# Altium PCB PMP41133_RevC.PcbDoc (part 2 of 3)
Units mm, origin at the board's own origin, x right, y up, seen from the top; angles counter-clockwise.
Board outline 150 x 82 mm, 4 copper layers (Top Layer, Int1 (GND), Int2 (PWR), Bottom Layer), stack 1.369 mm thick; 186 components, 74 nets, 388 pads, 329 vias.
Unrouted connection lines stored in the file: 2.
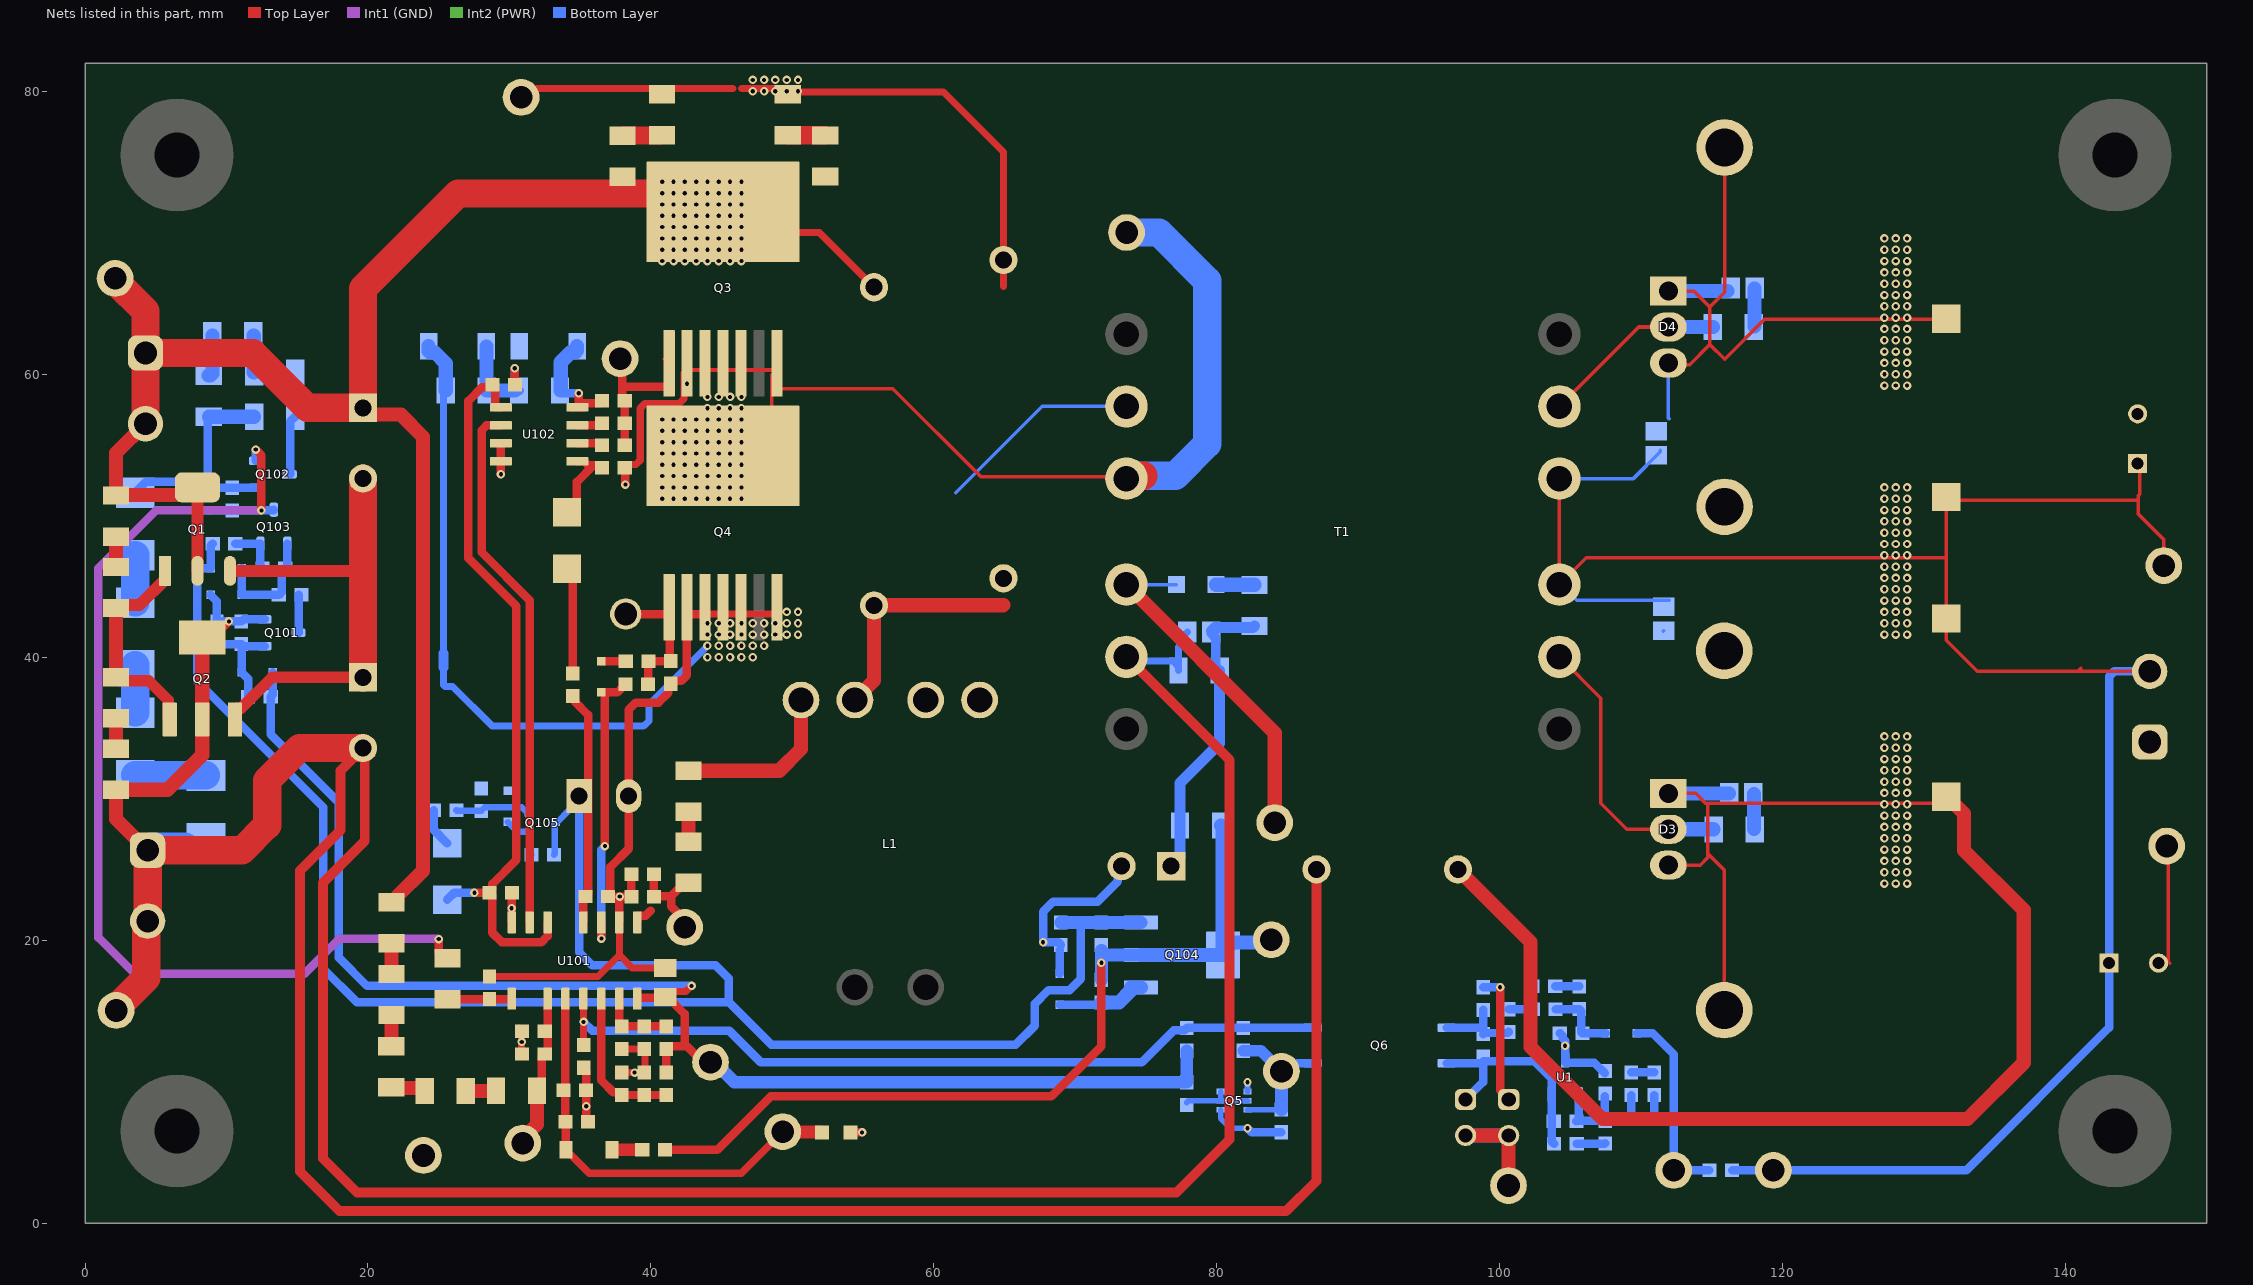
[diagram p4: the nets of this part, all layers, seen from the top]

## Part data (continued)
Q1: library part CMP-0089779-1, "Bipolar (BJT) Transistor NPN 600V 500mA  650mW Surface Mount SOT-223", Collector Base Voltage=600V, Digikey Part Number=1727-2369-1-ND, Emitter Base Voltage=6V, Manufacturer=Nexperia, Operating Temperature Range="to +150°C", Power_W=0.65W
Q2: library part CMP-0000371-2, "Transistor, PNP, 500 V, 0.25 A, AEC-Q101, SOT-223", Manufacturer="NXP Semiconductor", Supplier Part Number 1=568-5575-1-ND, Value1="0.25 A", Value2=300
Q3 Q4: library part CMP-0124581-1, "N-Channel 1200 V 8.1A (Tc) 80W (Tc) Surface Mount PG-TO263-7-12", Digikey Part Number=448-IMBG120R234M2HXTMA1CT-ND, Input Capacitance At Vds="1990pF @ 800V", Manufacturer=Infineon, Mouser Part Number=726-IMBG120R234M2HXT, Operating Temperature Range="-55°C to +175°C", Power_W=335W, Pulse Drain Current=159A, Typ Forward Diode Voltage=4.2V
Q5: library part CMP-0000396-2, "Transistor, Dual NPN, 40 V, 0.2 A, SOT-363", Manufacturer="Diodes Inc.", Supplier Part Number 1=MMDT3904-FDICT-ND, Value1="0.2 A", Value2=300
Q6: library part CMP-0121852-1, "3.75-kVRMS, Single-Channel Opto-Emulator with Analog Transistor Output", Emiiter Collector Voltage=7V, Forward Current=5mA, Manufacturer="Texas Instruments", Operating Temperature Range="to +150°C", Power_TotalModule=290mW, Voltage_Isolation_Vrms=3750Vrms
Q101: library part CMP-0085603-1, "MOSFET, N-CH, 60 V, 0.115 A, AEC-Q101, SOT-23", Alternate Manufacturer=None, Manufacturer="Diodes Inc.", Value1="? ohm", Value2="0.223 nC"
Q102 Q103: library part CMP-0067574-1, "MOSFET, N-CH, 600 V, 0.021 A, AEC-Q101, SOT-23", Alternate Manufacturer=None, Manufacturer="Infineon Technologies", Supplier Part Number 1=BSS126H6327XTSA2CT-ND, Value1="? ohm", Value2="1.4 nC"
Q104: library part CMP-0000393-1, "Transistor, NPN, 60 V, 3 A, SOT-223", Manufacturer=Zetex, Supplier Part Number 1=FZT651CT-ND, Value1="3 A", Value2=300
Q105: library part CMP-0000776-1, "MOSFET, N-CH, 60 V, 0.115 A, SOT-323", Alternate Manufacturer=None, Manufacturer="Diodes Inc.", Supplier Part Number 1=2N7002W-FDICT-ND, Value1=7
R1 R2 R3 R4: library part CMP-0018027-2, "RES, 1.00 M, 1%, 0.25 W, 1206", Manufacturer="Yageo America", Power_W=250mW, Supplier Part Number 1=311-1.00MFRCT-ND, TempCo="100 ppm/C", Tolerance_%=1%, Value2=0.25W, Value_Code=1M00, ValueDisplayed=1.00M
R5 R6: library part CMP-0022170-4, "RES, 1.00, 1%, 0.1 W, AEC-Q200 Grade 0, 0603", Manufacturer=Vishay-Dale, PartNumber=CRCW06031R00FKEA, Power_W=100mW, Supplier Part Number 1=52K8059, TempCo="100 ppm/C", Tolerance_%=1%, Value2=0.1W, Value_Code=1R00, ValueDisplayed=1.00
R7 R8: library part CMP-0022900-4, "RES, 1.00, 1%, 0.1 W, 0603", Manufacturer=Yageo, Power_W=100mW, Supplier Part Number 1=311-1.00HRCT-ND, TempCo="200 ppm/C", Tolerance_%=1%, Value2=0.1W, Value_Code=1R00, ValueDisplayed=1.00
R9 R10: library part CMP-0023167-5, "RES, 51.0 k, 1%, 0.1 W, 0603", Manufacturer=Yageo, Power_W=100mW, Supplier Part Number 1=311-51.0KHRCT-ND, TempCo="100 ppm/C", Tolerance_%=1%, Value2=0.1W, Value_Code=51k0, ValueDisplayed=51.0k
R11: library part CMP-0022938-5, "RES, 240, 1%, 0.1 W, 0603", Manufacturer=Yageo, Power_W=100mW, Supplier Part Number 1=311-240HRCT-ND, TempCo="100 ppm/C", Tolerance_%=1%, Value2=0.1W, Value_Code=240R, ValueDisplayed=240
R12: library part CMP-0018573-3, "RES, 0, 5%, 0.25 W, AEC-Q200 Grade 0, 1206", Manufacturer=Vishay-Dale, Power_W=250mW, Supplier Part Number 1=541-0.0ECT-ND, TempCo="200 ppm/C", Tolerance_%=5%, Value2=0.25W, Value_Code=0000, ValueDisplayed=0
R13 R15: library part CMP-0022872-5, "RES, 1.24 k, 1%, 0.1 W, 0603", Manufacturer=Yageo, Power_W=100mW, Supplier Part Number 1=311-1.24KHRCT-ND, TempCo="100 ppm/C", Tolerance_%=1%, Value2=0.1W, Value_Code=1k24, ValueDisplayed=1.24k
R14: library part CMP-0018693-3, "RES, 4.7, 5%, 0.25 W, AEC-Q200 Grade 0, 1206", Manufacturer=Vishay-Dale, Power_W=250mW, Supplier Part Number 1=541-4.7ECT-ND, TempCo="200 ppm/C", Tolerance_%=5%, Value2=0.25W, Value_Code=4R70, ValueDisplayed=4.7
R16: library part CMP-0025883-1, "RES, 0, 5%, 0.1 W, 0603", Manufacturer=Rohm, Power_W=100mW, Supplier Part Number 1=RHM0.0GCT-ND, TempCo="400 ppm/C", Tolerance_%=5%, Value2=0.1W, Value_Code=0000, ValueDisplayed=0
R17: library part CMP-0025697-4, "RES, 0, 5%, 0.1 W, AEC-Q200 Grade 0, 0603", Manufacturer=Vishay-Dale, Power_W=100mW, Supplier Part Number 1=541-0.0GCT-ND, TempCo="200 ppm/C", Tolerance_%=5%, Value2=0.1W, Value_Code=0000, ValueDisplayed=0
R18: library part CMP-0022117-4, "RES, 1.21 k, 1%, 0.1 W, AEC-Q200 Grade 0, 0603", Manufacturer=Vishay-Dale, Power_W=100mW, Supplier Part Number 1=541-1.21KHCT-ND, TempCo="100 ppm/C", Tolerance_%=1%, Value2=0.1W, Value_Code=1k21, ValueDisplayed=1.21k
R19: library part CMP-0023197-5, "RES, 5.11 k, 1%, 0.1 W, 0603", Manufacturer=Yageo, Power_W=100mW, Supplier Part Number 1=311-5.11KHRCT-ND, TempCo="100 ppm/C", Tolerance_%=1%, Value2=0.1W, Value_Code=5k11, ValueDisplayed=5.11k
R20: library part CMP-0022458-4, "RES, 4.99 k, 1%, 0.1 W, AEC-Q200 Grade 0, 0603", Manufacturer=Vishay-Dale, Power_W=100mW, Supplier Part Number 1=541-4.99KHCT-ND, TempCo="100 ppm/C", Tolerance_%=1%, Value2=0.1W, Value_Code=4k99, ValueDisplayed=4.99k
R21: library part CMP-0023337-1, "RES, 10.0 k, 1%, 0.1 W, 0603", Manufacturer="Vishay Draloric", Power_W=100mW, Supplier Part Number 1=541-1784-1-ND, TempCo="100 ppm/C", Tolerance_%=1%, Value2=0.1W, Value_Code=10k0, ValueDisplayed=10.0k
R22 R24: library part CMP-0017851-2, "RES, 10.0, 1%, 0.25 W, 1206", Manufacturer="Yageo America", Power_W=250mW, Supplier Part Number 1=311-10.0FRCT-ND, TempCo="200 ppm/C", Tolerance_%=1%, Value2=0.25W, Value_Code=10R0, ValueDisplayed=10.0
R25: library part CMP-0022339-4, "RES, 33.2 k, 1%, 0.1 W, AEC-Q200 Grade 0, 0603", Manufacturer=Vishay-Dale, Power_W=100mW, Supplier Part Number 1=541-33.2KHCT-ND, TempCo="100 ppm/C", Tolerance_%=1%, Value2=0.1W, Value_Code=33k2, ValueDisplayed=33.2k
R26: library part CMP-0022895-5, "RES, 1.00 k, 1%, 0.1 W, 0603", Manufacturer=Yageo, Power_W=100mW, Supplier Part Number 1=311-1.00KHRCT-ND, TempCo="100 ppm/C", Tolerance_%=1%, Value2=0.1W, Value_Code=1k00, ValueDisplayed=1.00k
R27: library part CMP-0022788-4, "RES, 137 k, 1%, 0.1 W, 0603", Manufacturer=Yageo, Power_W=100mW, Supplier Part Number 1=311-137KHRCT-ND, TempCo="100 ppm/C", Tolerance_%=1%, Value2=0.1W, Value_Code=137k
R28: library part CMP-0023279-5, "RES, 7.50 k, 1%, 0.1 W, 0603", Manufacturer=Yageo, Power_W=100mW, Supplier Part Number 1=311-7.50KHRCT-ND, TempCo="100 ppm/C", Tolerance_%=1%, Value2=0.1W, Value_Code=7k50, ValueDisplayed=7.50k
R29: library part CMP-0022206-3, "RES, 20.0, 1%, 0.1 W, 0603", Manufacturer=Vishay-Dale, PartNumber=CRCW060320R0FKEA, Power_W=100mW, Supplier Part Number 1=541-20.0HCT-ND, TempCo="100 ppm/C", Tolerance_%=1%, Value2=0.1W, Value_Code=20R0, ValueDisplayed=20.0
R101 R125 R127: library part CMP-0016959-3, "RES, 3.24 M, 1%, 0.25 W, AEC-Q200 Grade 0, 1206", Manufacturer=Vishay-Dale, Power_W=250mW, Supplier Part Number 1=541-3.24MFCT-ND, TempCo="100 ppm/C", Tolerance_%=1%, Value2=0.25W, Value_Code=3M24, ValueDisplayed=3.24M
R102: library part CMP-0022898-4, "RES, 1.50 M, 1%, 0.1 W, 0603", Manufacturer=Yageo, Power_W=100mW, Supplier Part Number 1=311-1.50MHRCT-ND, TempCo="100 ppm/C", Tolerance_%=1%, Value2=0.1W, Value_Code=1M50, ValueDisplayed=1.50M
R103: library part CMP-0025729-1, "RES, 1.0 k, 5%, 0.1 W, 0603", Manufacturer=Vishay-Dale, Power_W=100mW, Supplier Part Number 1=541-1.0KGCT-ND, TempCo="200 ppm/C", Tolerance_%=5%, Value2=0.1W, Value_Code=1k00, ValueDisplayed=1.0k
R104 R105: library part CMP-0022899-4, "RES, 1.00 M, 1%, 0.1 W, 0603", Manufacturer=Yageo, Power_W=100mW, Supplier Part Number 1=311-1.00MHRCT-ND, TempCo="100 ppm/C", Tolerance_%=1%, Value2=0.1W, Value_Code=1M00, ValueDisplayed=1.00M
R106: library part CMP-0022918-5, "RES, 220, 1%, 0.1 W, 0603", Manufacturer=Yageo, Power_W=100mW, Supplier Part Number 1=311-220HRCT-ND, TempCo="100 ppm/C", Tolerance_%=1%, Value2=0.1W, Value_Code=220R, ValueDisplayed=220
R107: library part CMP-0025701-2, "RES, 10 k, 5%, 0.1 W, 0603", Manufacturer=Vishay-Dale, Power_W=100mW, Supplier Part Number 1=541-10KGCT-ND, TempCo="200 ppm/C", Tolerance_%=5%, Value2=0.1W, Value_Code=10k0, ValueDisplayed=10k
R108 R109: library part CMP-0025874-2, "RES, 0, 5%, 0.1 W, 0603", Manufacturer=Panasonic, Power_W=100mW, Supplier Part Number 1=P0.0GCT-ND, TempCo="600 ppm/C", Tolerance_%=5%, Value2=0.1W, Value_Code=0000, ValueDisplayed=0
R110 R122: library part CMP-0022711-2, "RES, 2.20, 1%, 0.1 W, 0603", Manufacturer=Panasonic, Power_W=100mW, Supplier Part Number 1=P2.2AJCT-ND, TempCo="200 ppm/C", Tolerance_%=1%, Value2=0.1W, Value_Code=2R20, ValueDisplayed=2.20
R111 R112 R113 R123 R124: library part CMP-0016869-1, "RES, 2.43 M, 1%, 0.25 W, 1206", Manufacturer=Vishay-Dale, Power_W=250mW, Supplier Part Number 1=541-2.43MFCT-ND, TempCo="100 ppm/C", Tolerance_%=1%, Value2=0.25W, Value_Code=2M43, ValueDisplayed=2.43M
R114: library part CMP-0025790-4, "RES, 36 k, 5%, 0.1 W, AEC-Q200 Grade 0, 0603", Manufacturer=Vishay-Dale, Power_W=100mW, Supplier Part Number 1=541-36KGCT-ND, TempCo="200 ppm/C", Tolerance_%=5%, Value2=0.1W, Value_Code=36k0, ValueDisplayed=36k
R115: library part CMP-0023193-4, "RES, 590 k, 1%, 0.1 W, 0603", Manufacturer=Yageo, Power_W=100mW, Supplier Part Number 1=311-590KHRCT-ND, TempCo="100 ppm/C", Tolerance_%=1%, Value2=0.1W, Value_Code=590k
R116: library part CMP-0023259-5, "RES, 71.5 k, 1%, 0.1 W, 0603", Manufacturer=Yageo, Power_W=100mW, Supplier Part Number 1=311-71.5KHRCT-ND, TempCo="100 ppm/C", Tolerance_%=1%, Value2=0.1W, Value_Code=71k5, ValueDisplayed=71.5k
R117: library part CMP-0023210-4, "RES, 604 k, 1%, 0.1 W, 0603", Manufacturer=Yageo, Power_W=100mW, Supplier Part Number 1=311-604KHRCT-ND, TempCo="100 ppm/C", Tolerance_%=1%, Value2=0.1W, Value_Code=604k
R118: library part CMP-0022824-4, "RES, 165 k, 1%, 0.1 W, 0603", Manufacturer=Yageo, Power_W=100mW, Supplier Part Number 1=311-165KHRCT-ND, TempCo="100 ppm/C", Tolerance_%=1%, Value2=0.1W, Value_Code=165k
R119 R120: library part CMP-0023441-3, "RES, 15.0 k, 0.1%, 0.1 W, 0603", Manufacturer="Susumu Co Ltd", Power_W=100mW, Supplier Part Number 1=RG16P15.0KBCT-ND, TempCo="25 ppm/C", Tolerance_%=0.1%, Value2=0.1W, Value_Code=15k0, ValueDisplayed=15.0k
R121: library part CMP-0096703-1, "NTC Thermistor 470k 0603 (1608 Metric)", B Tolerance=3%, Digikey Part Number=495-B57371V2474J060CT-ND, Manufacturer=TDK, Mouser Part Number=871-B57371V2474J060, Operating Temperature Range="-55°C to +125°C", Power_W=180mW, Tolerance_%=5%
R126: library part CMP-0023257-4, "RES, 715 k, 1%, 0.1 W, 0603", Manufacturer=Yageo, Power_W=100mW, Supplier Part Number 1=311-715KHRCT-ND, TempCo="100 ppm/C", Tolerance_%=1%, Value2=0.1W, Value_Code=715k
R128: library part CMP-0018748-3, "RES, 0, 5%, 0.25 W, AEC-Q200 Grade 0, 1206", Manufacturer=Panasonic, Power_W=250mW, Supplier Part Number 1=P0.0ECT-ND, TempCo="600 ppm/C", Tolerance_%=5%, Value2=0.25W, Value_Code=0000, ValueDisplayed=0
R129: library part CMP-0022901-4, "RES, 200 k, 1%, 0.1 W, 0603", Manufacturer=Yageo, Power_W=100mW, Supplier Part Number 1=311-200KHRCT-ND, TempCo="100 ppm/C", Tolerance_%=1%, Value2=0.1W, Value_Code=200k
T1: library part Component_1, "Customized LLC transformer. Lp = 650uH", Manufacturer=Wurth
U1: library part CMP-0860484-1, "High-bandwidth low-IQ programmable shunt regulator, DBZ0003A (SOT-23-3)", Alternate Manufacturer="Texas Instruments", Operating Temperature Range="-40 to 85,-40 to 125 C", Rating=Catalog
U101: library part CMP-0095298-2, "750kHz Wide VIN/VOUT Range LLC Controller Optimized for Light Load Efficiency", Manufacturer="Texas Instruments", Max Supply Voltage=18.5V, Operating Temperature Range="-40°C to +150°C", Switching Frequency=30-750kHz
U102: library part CMP-0122620-1, "3kVrms, 5A/5A single-channel isolated gate driver with miller clamp or split out & 8V or 12V UVLO", Digikey Part Number=296-50190-1-ND, Manufacturer="Texas Instruments", Max Power Dissipation=1.14W, Max Supply Voltage=33V, Min Supply Voltage=3V, Mouser Part Number=595-UCC5350SBDR, Operating Temperature Range="-40°C to +125°C", Part Number=UCC5350SBDR

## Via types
v1: diameter 0.6, hole 0.3, Top Layer to Bottom Layer, tented both sides, 329 vias

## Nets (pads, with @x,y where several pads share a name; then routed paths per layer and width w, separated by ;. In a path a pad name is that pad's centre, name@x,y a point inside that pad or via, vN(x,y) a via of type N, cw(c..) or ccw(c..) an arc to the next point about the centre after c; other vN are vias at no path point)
5VP: 5VP.1 C108.1 D113.1 R13.2 R15.2 R115.2 R117.2 R126.2 U101.8 | length 98.2
  Top Layer w0.508: C108.1@40.945,15.924 C108.1@41.012,15.991 41.393,16.372 42.467,16.372 42.852,16.757 v1(42.877,16.757) v1@42.859,16.739 ; R117.2@41.106,10.644 R117.2@41.125,10.625
  Top Layer w0.6: U101.8@39.043,15.857 39.043,15.924 C108.1@40.945,15.924 ; C108.1@41.012,15.991 41.177,15.991 42.388,14.781 42.388,12.512 ; R117.2@41.1,10.65 R115.2@41.1,12.3 41.1,12.325 41.275,12.5 42.546,12.5 43.673,11.373 5VP.1@44.214,11.373
  Bottom Layer w0.6: D113.1@13.275,38.925 13.275,37.35 R126.2@13.125,37.2 13.125,34.546 17.933,29.737 17.933,18.767 19.943,16.757 v1(42.877,16.757) ; 5VP.1@44.214,11.373 5VP.1@44.48,11.373
  Bottom Layer w0.9: 5VP.1@44.48,11.373 45.903,9.95 R13.2@77.875,9.95 R15.2@77.875,12.175
BLK: BLK.1 C105.1 R113.1 R114.2 U101.3 | length 10.3
  Top Layer w0.6: R113.1@32.301,9.532 32.301,11.775 32.476,11.95 R114.2@32.5,11.95 ; R114.2@32.693,12.155 U101.3@32.693,15.857
  Top Layer w1: BLK.1@30.944,5.65 30.944,5.969 31.95,6.975 R113.1@31.95,9.35
FB: C9.1 C29.1 Q6.4 R15.1 U101.5 | length 57
  Top Layer w0.508: U101.5@35.233,15.857 35.242,15.849 v1(35.242,14.216) 35.242,12.583 C9.1@35.25,12.575
  Bottom Layer w0.6: v1(35.242,14.216) 35.87,13.588 45.545,13.588 47.772,11.362 74.713,11.362 76.977,13.625 77.725,13.625 77.9,13.8 81.875,13.8 Q6.4@86.785,13.8
HB: C107.1 C111.1 D108.1 U101.14 U102.1 | length 52.7
  Top Layer w0.6: v1(27.525,23.35) C107.1@28.594,23.35 C107.1@28.615,23.35 ; U102.1@29.4,57.655 29,57.655 29,59.075 28.825,59.25 C111.1@28.8,59.25 28.625,59.075 28.061,59.075 27.104,58.118 27.104,46.997 30.5,43.602 30.5,25.678 28.794,23.972 28.794,23.525 28.619,23.35 C107.1@28.615,23.35 ; U101.14@32.693,21.257 32.693,20.278 32.266,19.85 29.464,19.85 28.79,20.524 28.79,23.175 C107.1@28.615,23.35
  Bottom Layer w0.6: D108.1@25.6,22.85 26.1,23.35 v1(27.525,23.35)
HO: R6.1 U102.6 | length 1.8
  Top Layer w0.6: U102.6@34.8,55.115 36.41,55.115 R6.1@36.55,54.975
HO_CTRL: U101.15 U102.2 | length 58.2
  Top Layer w0.254: 31.31,41.689 31.31,21.371 U101.15@31.423,21.257
  Top Layer w0.6: U102.2@29.4,56.385 28.379,56.385 28.028,56.034 28.028,47.422 31.423,44.027 U101.15@31.423,21.257
HO_OFF: R7.1 U102.7 | length 1.8
  Top Layer w0.6: U102.7@34.8,56.385 36.385,56.385 R7.1@36.55,56.55
HS: C112.1 C114.1 D110.1 Q3.2 Q3.3 Q3.4 Q3.5 Q3.7 Q4.8 R9.1 SW.1 T1.3 U102.8 | length 89.9
  Top Layer w0.25: Q3.2@42.56,60.3 43.83,60.3 45.1,60.3 46.37,60.3 47.64,60.3 Q3.7@48.91,60.3 ; Q4.8@47.782,52.77 48.56,53.548 48.56,59.95 Q3.7@48.91,60.3 ; T1.3@73.618,52.625 73.473,52.77 63.312,52.77 57.104,58.977 49.26,58.977 48.91,59.327 Q3.7@48.91,60.3
  Top Layer w0.5: C114.1@38.325,53.575 38.375,53.625 38.958,53.625 39.251,53.918 39.251,57.593 39.602,57.944 42.015,57.944 42.337,58.267 42.337,60.077 Q3.2@42.56,60.3
  Top Layer w0.6: U102.8@34.375,57.655 U102.8@34.8,57.655 U102.8@34.9,57.655 ; v1(34.9,58.65) U102.8@34.9,57.655 ; U102.8@34.931,57.95 36.375,57.95 R9.1@36.55,58.125 ; U102.8@35.275,57.655 U102.8@34.9,57.655 ; v1(38.2,52.2) 38.2,53.45 C114.1@38.325,53.575
  Top Layer w2: T1.3@73.618,52.625 73.809,52.816 T1.3@74.824,52.816
  Bottom Layer w0.25: v1@42.551,59.327 v1(42.56,59.327)
  Bottom Layer w0.6: C112.1@33.575,58.85 33.775,58.65 v1(34.9,58.65)
  Bottom Layer w1: C112.1@33.625,58.85 33.625,60.845 34.335,61.555 34.66,61.555 34.78,61.675 D110.1@34.78,62
  Bottom Layer w2: T1.3@73.618,52.625 73.809,52.816 77.065,52.816 79.323,55.075 79.323,66.613 75.917,70.02 SW.1@73.629,70.02
  other v1: 40.8,51.2 41.6,51.2 42.4,51.2 43.2,51.2 44,51.2 44.8,51.2 45.6,51.2 46.4,51.2 40.8,52 41.6,52 42.4,52 43.2,52 44,52 44.8,52 45.6,52 46.4,52 40.8,52.8 41.6,52.8 42.4,52.8 43.2,52.8 44,52.8 44.8,52.8 45.6,52.8 46.4,52.8 40.8,53.6 41.6,53.6 42.4,53.6 43.2,53.6 44,53.6 44.8,53.6 45.6,53.6 46.4,53.6 40.8,54.4 41.6,54.4 42.4,54.4 43.2,54.4 44,54.4 44.8,54.4 45.6,54.4 46.4,54.4 40.8,55.2 41.6,55.2 42.4,55.2 43.2,55.2 44,55.2 44.8,55.2 45.6,55.2 46.4,55.2 40.8,56 41.6,56 42.4,56 43.2,56 44,56 44.8,56 45.6,56 46.4,56 40.8,56.8 41.6,56.8 42.4,56.8 43.2,56.8 44,56.8 44.8,56.8 45.6,56.8 46.4,56.8 44,57.6 44.8,57.6 45.6,57.6 46.4,57.6 44,58.4 44.8,58.4 45.6,58.4 46.4,58.4
HS_CTRL: C107.2 C111.2 C112.2 C113.1 D110.2 D111.1 U101.16 U102.3 U102.4 | length 12.5
  Top Layer w0.6: v1(29.4,52.925) U102.4@29.4,53.845 U102.3@29.4,55.115 ; U101.16@30.153,21.257 30.153,23.303 C107.2@30.375,23.525 ; v1(30.375,60.425) 30.375,59.275 C111.2@30.4,59.25
  Bottom Layer w0.254: v1@29.425,52.825 v1@29.519,52.825 ; C112.2@30.725,58.74 C112.2@30.825,58.74
  Bottom Layer w0.6: v1(30.375,60.425) 30.375,59.2 C112.2@30.725,58.85
  Bottom Layer w1: C113.1@28.383,59.068 D111.1@28.383,61.957 ; C113.1@28.4,58.85 C112.2@30.375,58.85
  other v1: 30.15,22.25
ISNS: C6.2 C7.1 ISNS.1 R11.2 U101.9 | length 8.6
  Top Layer w0.6: U101.9@39.043,21.257 39.043,21.732 39.638,21.732 39.989,22.083 ; R11.2@40.189,24.657 40.189,23.107 40.197,23.115 41.44,23.115 ; ISNS.1@42.388,20.898 42.388,21.439 41.44,22.386 41.44,23.115 ; C6.2@42.65,24.05 42.375,24.05 41.44,23.115
LL: C109.1 R117.1 R118.2 U101.6 | length 10.8
  Top Layer w0.508: R117.1@41.063,9.062 R117.1@41.075,9.05
  Top Layer w0.6: U101.6@36.503,15.857 36.503,10.087 37.341,9.249 37.798,9.249 37.973,9.074 C109.1@37.973,9.05 ; C109.1@37.95,9.05 R118.2@39.525,9.05 R117.1@41.075,9.05
LO: D1.1 R5.1 U101.11 | length 20.7
  Top Layer w0.6: v1(36.503,20.107) U101.11@36.503,21.257 ; D1.1@36.503,37.509 36.975,37.509 ; v1(36.75,26.65) 36.75,37.283 36.975,37.509 ; R5.1@38.2,38.075 38.175,38.075 38,37.9 38,37.875 37.634,37.509 36.975,37.509
  Bottom Layer w0.6: v1(36.503,20.107) 36.503,26.403 v1(36.75,26.65)
NetC1_2: C1.2 C2.1 Q1.3 Q2.3 | length 76.3
  Top Layer w0.8: Q2.3@10.59,35.586 10.59,36.286 10.69,36.386 11.034,36.386 13.223,38.575 C2.1@19.65,38.575 ; 19.614,46.089 19.65,46.125
  Top Layer w0.85: Q1.3@10.269,46.089 19.614,46.089
  Top Layer w2: C2.1@19.65,38.575 19.65,46.125 C1.2@19.65,52.625
  Int1 (GND) w2: C2.1@19.65,38.575 C1.2@19.65,52.625
  Int2 (PWR) w2: C2.1@19.65,38.575 C1.2@19.65,52.625
  Bottom Layer w2: C2.1@19.65,38.575 C1.2@19.65,52.625
NetC3_2: C3.2 C4.1 C5.1 L1.4 L1.5 | length 28.5
  Top Layer w1: C5.1@42.65,31.975 49.075,31.975 50.613,33.513 L1.5@50.613,36.972 ; L1.4@54.423,36.972 54.423,37.006 55.775,38.358 C3.2@55.775,43.65 55.8,43.675 64.9,43.675 64.925,43.7
NetC5_2: C5.2 C6.1 | length 2.1
  Top Layer w1: C6.1@42.65,26.95 C5.2@42.65,29.075
NetC8_1: C8.1 C10.1 C11.1 R12.2 R14.1 | length 21.4
  Bottom Layer w0.7: C8.1@79.625,41.775 79.625,41.675 79.931,41.369 79.931,39.319 C10.1@80.2,39.05
  Bottom Layer w0.8: C11.1@76.775,25.225 77.4,25.85 R12.2@77.4,28.1 77.4,31.1 80.2,33.9 C10.1@80.2,39.05 ; C8.1@79.625,41.845 79.875,42.095 82.57,42.095 R14.1@82.675,42.2
NetC12_1: C12.1 C13.1 D5.2 R19.2 | length 5.1
  Bottom Layer w0.6: R19.2@103.95,15.125 C13.1@105.625,15.125 105.784,14.966 105.784,13.491 C12.1@105.85,13.425 D5.2@107.5,13.425
NetC13_2: C13.2 R18.2 | length 1.7
  Bottom Layer w0.6: R18.2@103.925,16.725 C13.2@105.625,16.725
NetC14_1: C14.1 R22.1 | length 2.6
  Bottom Layer w0.508: C14.1@117.926,30.365 C14.1@117.976,30.315 ; R22.1@117.976,27.875 R22.1@118.026,27.825
  Bottom Layer w1: R22.1@117.976,27.875 C14.1@117.976,30.315
NetC15_1: C15.1 C17.2 J3.1 Q6.2 R21.1 U1.2 | length 15.9
  Bottom Layer w0.6: Q6.2@96.25,11.3 98.7,11.3 R21.1@98.825,11.425 ; J3.1@97.593,8.731 98.825,9.963 R21.1@98.825,11.425 ; C15.1@103.85,5.6 103.675,5.775 U1.2@103.675,9.1 103.675,10.225 102.475,11.425 R21.1@98.825,11.425
NetC15_2: C15.2 R25.2 | length 2
  Bottom Layer w0.6: C15.2@105.45,5.6 105.462,5.613 107.437,5.613 R25.2@107.45,5.625
NetC16_1: C16.1 R24.1 | length 2.8
  Bottom Layer w0.508: R24.1@117.975,63.34 R24.1@118.004,63.369 ; C16.1@118.004,66.071 C16.1@118.033,66.1
  Bottom Layer w1: R24.1@118.004,63.369 C16.1@118.004,66.071
NetC17_1: C17.1 R25.1 R26.1 R27.1 R28.2 U1.1 | length 9.2
  Bottom Layer w0.6: C17.1@105.425,7.2 C17.1@105.438,7.213 ; C17.1@105.463,7.238 C17.1@105.438,7.213 ; C17.1@105.575,7.375 U1.1@105.575,9.1 ; R28.2@107.425,8.975 107.437,8.963 107.437,7.338 R25.1@107.5,7.275 ; R27.1@109.309,7.325 109.259,7.275 R25.1@107.5,7.275 ; R27.1@109.309,7.325 R26.1@109.31,9.049 ; C17.1@105.438,7.213 107.438,7.213 R25.1@107.45,7.225 R25.1@107.5,7.275
NetC19_1: C19.1 D5.1 Inj1.1 R27.2 R29.1 | length 17.1
  Bottom Layer w0.6: D5.1@109.7,13.425 110.814,13.425 112.3,11.939 112.3,7.275 ; C19.1@110.925,9.05 110.917,9.042 110.917,7.333 R27.2@110.909,7.325 112.25,7.325 112.3,7.275 ; R29.1@114.825,3.725 Inj1.1@112.3,3.725 112.3,7.275
NetC19_2: C19.2 R26.2 | length 1.6
  Bottom Layer w0.6: R26.2@109.31,10.65 C19.2@110.925,10.65
NetC25_2: C25.2 C26.1 | length 2.8
  Top Layer w1: C25.2@38,76.85 C25.2@38.025,76.875 ; C26.1@40.75,76.875 C26.1@40.775,76.9
  Top Layer w1.3: C25.2@38.025,76.875 C26.1@40.75,76.875
NetC27_2: C27.2 C28.1 | length 2.7
  Top Layer w1: C28.1@49.675,76.9 C28.1@49.688,76.887 ; C27.2@52.313,76.887 C27.2@52.325,76.875
  Top Layer w1.3: C28.1@49.688,76.887 C27.2@52.313,76.887
NetC29_2: C29.2 I_opt.1 Q5.3 Q6.3 R16.2 | length 10.9
  Bottom Layer w0.4: Q5.3@82.175,8 84.562,8 R16.2@84.575,8.013
  Bottom Layer w0.508: Q6.3@86.739,11.254 Q6.3@86.785,11.3
  Bottom Layer w0.6: I_opt.1@84.575,10.725 85.116,10.725 85.691,11.3 Q6.3@86.785,11.3
  Bottom Layer w0.8: C29.2@81.875,12.175 83.125,12.175 I_opt.1@84.575,10.725
  Bottom Layer w0.9: R16.2@84.575,8.013 I_opt.1@84.575,10.725
NetC101_1: C101.1 D101.1 D114.2 Q102.1 R101.1 R104.1 | length 16.8
  Bottom Layer w0.6: D101.1@3.55,51.635 4.329,52.415 8.339,52.415 8.499,52.575 D114.2@8.675,52.575 ; R101.1@8.753,56.997 8.675,56.92 D114.2@8.675,52.575 ; Q102.1@12.075,51.975 R104.1@10.4,51.975 9.275,51.975 D114.2@8.675,52.575
  Bottom Layer w1: R101.1@8.753,56.997 11.947,56.997 C101.1@11.95,56.995
NetC102_1: C102.1 D113.2 Q101.1 R102.2 R126.1 | length 7.1
  Bottom Layer w0.6: R102.2@9.329,40.925 C102.1@11.057,40.925 C102.1@11.075,40.907 ; C102.1@11.079,40.903 C102.1@11.075,40.907 ; C102.1@11.207,40.775 Q101.1@12.7,40.775 ; R126.1@11.525,37.2 11.525,38.475 D113.2@11.075,38.925 C102.1@11.075,40.907
NetC114_2: C114.2 D112.1 U102.5 | length 5.4
  Top Layer w0.6: D112.1@34.075,50.25 34.775,50.95 34.775,52.39 35.96,53.575 35.545,53.575 35.275,53.845 U102.5@34.8,53.845
NetC116_1: C116.1 Q105.2 R110.1 | length 5.4
  Bottom Layer w0.45: R110.1@26.25,29.175 26.275,29.15 27.975,29.15 C116.1@28,29.125 ; C116.1@28,29.15 28.248,29.398 30.862,29.398 31.3,28.96 31.365,28.96 Q105.2@31.375,28.95
NetD1_2: D1.2 R8.1 | length 1.9
  Top Layer w0.508: R8.1@38.096,39.854 R8.1@38.225,39.725
  Top Layer w0.6: D1.2@36.503,39.709 38.025,39.709 38.096,39.78 R8.1@38.096,39.854
NetD2_1: D2.1 R14.2 | length 2.7
  Bottom Layer w1: D2.1@79.95,45.132 79.966,45.116 82.659,45.116 R14.2@82.675,45.1
NetD2_2: D2.2 T1.4 VAUX.1 | length 24.7
  Top Layer w1: T1.4@73.618,45.132 84.1,34.65 VAUX.1@84.1,28.3
  Bottom Layer w0.25: T1.4@73.618,45.132 D2.2@77.15,45.132
NetD101_2: D101.2 D102.1 | length 3.4
  Bottom Layer w2: D102.1@3.55,43.86 D101.2@3.55,47.215
NetD102_2: D102.2 D103.1 | length 3.4
  Bottom Layer w2: D103.1@3.55,36.085 D102.2@3.55,39.44
NetD103_2: D103.2 D104.1 | length 5
  Bottom Layer w2: D103.2@3.55,31.665 3.565,31.65 8.535,31.65 D104.1@8.55,31.635
NetD105_1: D105.1 D106.2 Q103.1 R103.2 R105.1 | length 8.1
  Bottom Layer w0.6: D106.2@11.075,46.3 D105.1@11.075,44.4 R103.2@13.35,44.4 ; R103.2@13.5,44.4 13.725,44.4 13.9,44.575 13.9,45.775 13.95,45.825 13.95,46.125 14.125,46.3 R105.1@14.15,46.3 ; R105.1@14.3,46.45 Q103.1@14.3,48.025
NetD107_1: D107.1 Q104.1 R107.2 | length 6.1
  Bottom Layer w0.6: D107.1@68.9,15.425 R107.2@71.7,15.425
  Bottom Layer w1: R107.2@71.85,15.6 73.094,15.6 73.95,16.456 73.95,16.65 Q104.1@74.65,16.65
NetD108_2: D108.2 R110.2 | length 2.7
  Bottom Layer w0.6: R110.2@24.65,29.175 24.65,27.8 D108.2@25.6,26.85
NetD109_1: D109.1 R120.1 | length 2.1
  Top Layer w0.9: D109.1@37.263,5.175 R120.1@39.389,5.175
NetD112_2: D112.2 R122.2 | length 7.6
  Top Layer w0.6: D112.2@34.075,46.25 34.475,45.85 R122.2@34.475,38.85
NetD114_1: D114.1 Q102.2 Q103.3 R104.2 R128.1 | length 77.3
  Top Layer w0.6: v1(12.075,54.675) 12.475,54.275 v1(12.475,50.375) ; v1(25,20.075) 25,19.075 25.35,18.725 R128.1@25.625,18.725 ; R128.1@26.025,18.55 R128.1@26.05,18.55
  Int1 (GND) w0.6: v1(12.475,50.375) 5.025,50.375 0.95,46.3 0.95,20.176 3.49,17.635 15.529,17.635 18,20.107 24.968,20.107 v1(25,20.075)
  Bottom Layer w0.5: Q103.3@13.333,50.442 Q103.3@13.35,50.425
  Bottom Layer w0.6: D114.1@8.675,50.375 R104.2@10.4,50.375 v1(12.475,50.375) 13.35,50.375 Q103.3@13.35,50.425 ; Q102.2@12.075,53.875 v1(12.075,54.675)
NetD115_1: D115.1 Q105.1 R129.1 | length 3.5
  Bottom Layer w0.45: D115.1@29.875,28.35 30.575,27.65 Q105.1@31.375,27.65 31.44,27.65 31.45,27.64 31.45,26.125 R129.1@31.55,26.025
NetHG_1: HG.1 Q3.1 R6.2 R7.2 R9.2 | length 11.6
  Top Layer w0.254: Q3.1@40.942,61.1 41.29,60.752 Q3.1@41.29,60.3
  Top Layer w0.6: HG.1@37.825,61.1 37.988,60.937 37.988,59.105 ; R6.2@38.15,54.975 R7.2@38.15,56.55 R9.2@38.15,58.125 37.988,58.287 37.988,59.105 ; Q3.1@41.29,60.3 41.29,59.28 41.115,59.105 37.988,59.105
NetJ4_1: J4.1 R20.2 | length 9.4
  Top Layer w0.6: v1(100.025,16.666) 100.025,9.382 100.64,8.767 J4.1@100.64,8.726
  Bottom Layer w0.6: R20.2@98.825,16.666 v1(100.025,16.666)
NetL1_2: L1.2 L1.3 T1.2 | length 15.2
  Bottom Layer w0.25: 61.55,51.625 67.655,57.73 T1.2@73.618,57.73 ; L1.2@62.823,37.386 L1.2@63.237,36.972
NetLG_1: LG.1 Q4.1 R5.2 R8.2 R10.2 | length 9.7
  Top Layer w0.6: LG.1@38.223,43.05 41.29,43.05 41.345,42.995 41.345,39.78 R10.2@41.4,39.725 R8.2@39.825,39.725 39.812,39.713 39.812,38.087 R5.2@39.8,38.075
NetQ1_1: Q1.1 Q2.1 R2.1 R3.2 | length 15.6
  Top Layer w0.8: R3.2@2.2,38.589 2.446,38.342 4.494,38.342 5.89,36.947 5.89,35.686 Q2.1@5.99,35.586
  Top Layer w0.85: R2.1@2.2,43.475 2.425,43.7 3.866,43.7 5.65,45.484 Q1.1@5.65,46.1
  Top Layer w1: R3.2@2.2,38.589 R2.1@2.2,43.475
NetQ5_2: Q5.2 Q5.5 Q5.6 R13.1 | length 5
  Bottom Layer w0.4: R13.1@77.875,8.5 78.025,8.65 Q5.5@80.275,8.65 ; Q5.6@80.275,9.3 Q5.5@80.275,8.65 ; Q5.2@82.175,8.65 Q5.5@80.275,8.65
NetQ6_1: Q6.1 R17.1 R20.1 R21.2 | length 5.8
  Bottom Layer w0.6: Q6.1@96.25,13.8 98.8,13.8 98.825,13.775 R20.1@98.825,15.066 ; R21.2@98.825,13.35 98.908,13.433 100.554,13.433 R17.1@100.637,13.516 R17.1@100.637,13.491
NetQ101_3: Q101.3 R103.1 | length 2.8
  Bottom Layer w0.5: Q101.3@15.025,41.775 15.075,41.725 Q101.3@15.1,41.725
  Bottom Layer w0.6: Q101.3@15.1,41.725 R103.1@15.1,44.4
NetQ103_2: Q103.2 R105.2 R106.2 | length 3.6
  Bottom Layer w0.6: R106.2@10.625,48.025 Q103.2@12.4,48.025 12.4,46.45 R105.2@12.55,46.3
NetR1_1: R1.1 R2.2 | length 2.2
  Top Layer w1: R2.2@2.2,46.375 R1.1@2.2,48.525
NetR3_1: R3.1 R4.2 | length 2.2
  Top Layer w1: R4.2@2.2,33.525 R3.1@2.2,35.689
NetR17_2: R17.2 R18.1 R19.1 | length 3.3
  Bottom Layer w0.6: R17.2@100.637,15.116 100.642,15.12 102.345,15.12 R19.1@102.35,15.125 102.337,15.138 102.337,16.712 R18.1@102.325,16.725
NetR101_2: R101.2 R125.1 | length 3
  Bottom Layer w1: R101.2@8.75,59.9 8.85,59.9 9,60.05 R125.1@9,62.75
NetR109_1: R109.1 R128.2 U101.1 | length 4.5
  Top Layer w0.5: U101.1@30.141,15.844 U101.1@30.153,15.857
  Top Layer w0.6: R128.2@25.625,15.825 25.628,15.828 28.591,15.828 R109.1@28.594,15.832 30.128,15.832 U101.1@30.141,15.844
NetR111_1: R111.1 R112.2 | length 2.5
  Top Layer w1: R111.1@21.65,9.605 21.707,9.548 23.875,9.548 24.025,9.398 R112.2@24.025,9.325
NetR111_2: R111.2 R124.1 | length 2.2
  Top Layer w1: R111.2@21.65,12.505 21.66,12.515 21.66,14.697 R124.1@21.67,14.707
NetR112_1: R112.1 R113.2 | length 2.1
  Top Layer w1: R112.1@26.925,9.325 26.938,9.337 29.038,9.337 R113.2@29.05,9.35
NetR123_1: R123.1 R124.2 | length 2.2
  Top Layer w1: R124.2@21.67,17.607 R123.1@21.67,19.783
NetR125_2: R125.2 R127.1 | length 2.7
  Bottom Layer w1: R125.2@11.9,62.75 11.925,62.725 11.925,60.137 R127.1@11.95,60.112
OVP/OTP: C110.1 D109.2 OVP_OTP.1 R119.2 R121.2 U101.4 | length 30.8
  Top Layer w0.508: U101.4@33.963,15.857 U101.4@33.975,15.845 ; D109.2@33.988,5.022 34.191,4.819 34.344,4.819 35.638,3.525 46.393,3.525 OVP_OTP.1@49.325,6.457
  Top Layer w0.6: U101.4@33.963,15.857 R119.2@33.963,7.15 33.975,7.138 33.975,5.035 D109.2@33.988,5.022
  Top Layer w0.9: OVP_OTP.1@49.325,6.457 49.354,6.429 52.071,6.429 R121.2@52.1,6.4
PGND: C2.2 C4.2 C7.2 C8.2 C9.2 C10.2 C11.2 C26.2 C28.2 C102.2 C103.2 C104.2 C105.2 C106.2 C108.2 C109.2 C110.2 C113.2 C115.2 C116.2 CY1.2 D104.2 D105.2 D107.2 D111.2 D115.2 J2.1 J2.2 PGND.1 Q2.2 Q2.4 Q4.2 Q4.3 Q4.4 Q4.5 Q4.7 Q5.1 Q5.4 Q101.2 R4.1 R10.1 R11.1 R16.1 R102.1 R109.2 R114.1 R116.1 R118.1 R119.1 R121.1 T1.5 U101.10 | length 513.3
  Top Layer w0.5: R109.2@28.594,17.432 36.271,17.432 37.773,18.935 ; C105.2@30.697,13.772 C105.2@30.9,13.57 ; PGND.1@30.825,79.575 31.288,79.575 31.913,80.2 45.789,80.2 ; R114.1@30.868,11.955 C105.2@30.868,13.575 ; R119.1@35.538,7.15 R119.1@35.563,7.15 ; U101.10@37.773,21.257 37.773,18.935 ; C109.2@37.973,10.649 37.986,10.637 v1(38.851,10.637) 39.564,10.637 39.576,10.625 39.576,12.3 C106.2@37.975,12.3 ; C108.2@41.012,18.023 38.685,18.023 37.773,18.935 ; Q4.3@43.83,43.05 45.1,43.05 46.37,43.05 47.64,43.05 48.91,43.05 Q4.7@48.865,43.005 ; 46.419,80.189 48.861,80.189 C28.2@49.25,79.8 ; C28.2@49.16,79.95 60.675,79.95 64.925,75.7 ; 64.925,66.2 64.925,75.7 ; C4.2@64.925,68.075 64.925,75.7
  Top Layer w0.6: Q2.4@8.399,41.426 9.076,41.426 v1(10.175,42.525) ; C9.2@35.25,10.975 35.25,10.95 35.425,10.775 C110.2@35.425,9.374 v1(35.425,8.25) 35.425,7.263 R119.1@35.538,7.15 ; U101.10@37.773,21.257 37.773,23.03 v1@37.725,23.078 ; C7.2@38.589,23.082 C7.2@38.586,23.078 ; R11.1@38.625,24.596 C7.2@38.625,23.075 38.622,23.078 C7.2@38.586,23.078 ; Q4.2@42.538,43.028 42.538,38.706 42.157,38.325 41.575,38.325 41.4,38.15 R10.1@41.4,38.125 41.225,37.95 41.225,37.477 40.542,36.794 38.935,36.794 38.432,36.291 38.432,26.46 37.145,25.173 37.145,23.252 C104.2@36.975,23.082 36.979,23.078 v1@37.725,23.078 ; Q4.2@42.56,43.05 Q4.3@43.83,43.05 ; R121.1@54.1,6.4 v1(54.925,6.4) ; v1@37.725,23.078 C7.2@38.586,23.078
  Top Layer w0.7: T1.5@73.618,40.027 80.9,32.745 80.9,5.899 77.155,2.154 19.231,2.154 16.832,4.553 16.832,24.051 19.775,26.995 19.775,33.45 C2.2@19.65,33.575 18.073,31.998 18.073,27.774 15.204,24.906 15.204,3.643 17.997,0.85 84.918,0.85 87.05,2.982 CY1.2@87.05,25
  Top Layer w1: J2.1@4.425,26.344 2.2,28.569 R4.1@2.2,30.625 5.84,30.625 8.29,33.075 Q2.2@8.29,35.586 Q2.4@8.29,41.386
  Top Layer w2: PGND.1@2.2,15.025 2.2,15.187 4.329,17.317 4.329,21.248 J2.2@4.425,21.344 J2.1@4.425,26.344 11.094,26.344 12.875,28.125 12.875,31.277 15.173,33.575 C2.2@19.65,33.575
  Bottom Layer w0.4: Q5.4@80.275,8 80.275,7.4 80.975,6.7 v1(82.175,6.7) ; Q5.1@82.175,9.3 v1(82.175,9.95)
  Bottom Layer w0.5: 25.337,39.262 25.337,38.038 25.45,37.925 25.987,37.925 28.785,35.127 39.491,35.127 39.864,35.5 39.864,36.664 v1(44,40.8) ; 25.337,40.275 C113.2@25.337,58.85 ; T1.5@73.618,40.027 73.92,39.725 76.9,39.725 C10.2@77.3,39.325 ; C10.2@77.3,39.05 C10.2@77.3,39.325 ; C8.2@77.925,41.775 77.525,41.375 77.525,40.95 77.3,40.725 C10.2@77.3,39.325
  Bottom Layer w0.6: D105.2@8.875,44.4 9.329,43.947 R102.1@9.329,42.525 C102.2@11.057,42.525 11.207,42.675 Q101.2@12.7,42.675 ; D107.2@68.9,17.625 C103.2@68.9,19.3 ; C103.2@68.975,19.65 68.975,19.675 68.8,19.85 v1(67.725,19.85) 67.725,22.007 68.429,22.71 71.575,22.71 73.007,24.143 73.007,24.957 C11.2@73.275,25.225 ; v1(82.175,6.7) 82.462,6.413 R16.1@84.575,6.413
  Bottom Layer w0.7: 25.337,39.262 25.337,40.275
  Bottom Layer w1: D111.2@24.285,61.975 24.285,61.65 24.405,61.53 24.73,61.53 25.5,60.76 C113.2@25.5,58.85
  Bottom Layer w2: J2.1@4.425,26.344 4.675,26.594 7.062,26.594
  other v1: 30.868,12.8 37.8,23.075 44,40 44.8,40 45.6,40 46.4,40 47.2,40 44.8,40.8 45.6,40.8 46.4,40.8 47.2,40.8 48,40.8 44,41.6 44.8,41.6 45.6,41.6 46.4,41.6 47.2,41.6 48,41.6 48.8,41.6 49.6,41.6 50.4,41.6 44,42.4 44.8,42.4 45.6,42.4 46.4,42.4 47.2,42.4 48,42.4 48.8,42.4 49.6,42.4 50.4,42.4 49.6,43.2 50.4,43.2 47.2,80 48,80 48.8,80 49.6,80 50.4,80 47.2,80.8 48,80.8 48.8,80.8 49.6,80.8 50.4,80.8
SGND: C12.2 C14.2 C16.2 C18.2 C20.2 C21.2 C22.2 C23.1 C24.1 CY1.1 D3.1 D3.3 D4.1 D4.3 H1.1 H1.2 H2.1 H2.2 J3.2 J4.2 J5.1 R28.1 SGND2.1 SGND.1 U1.3 | length 189.4
  Top Layer w0.25: J3.2@97.012,6.414 J3.2@97.015,6.411 ; D3.3@111.925,25.295 114.17,25.295 114.725,25.85 114.725,26.1 ; D3.1@111.925,30.375 113.85,30.375 114.55,29.675 114.725,29.675 ; D4.3@111.925,60.8 112.046,60.679 113.429,60.679 114.85,62.1 ; D4.1@111.925,65.88 113.72,65.88 114.85,64.75 ; H2.2@115.875,15.05 115.875,24.95 114.725,26.1 ; H2.1@115.875,39.957 H2.1@115.875,40.45 ; H1.1@115.9,76.025 115.9,65.8 114.85,64.75 ; 131.575,30.19 131.06,29.675 114.725,29.675 ; 131.575,63.875 118.725,63.875 115.9,61.05 114.85,62.1 ; SGND.1@147.15,26.65 147.262,26.538 147.262,18.487 147.375,18.375 ; 114.725,26.1 114.725,29.675 ; 114.85,62.1 114.85,64.75
  Top Layer w1: CY1.1@97.05,25 102.175,19.875 102.175,12.434 107.259,7.35 133.064,7.35 137.047,11.333 137.047,22.116 132.825,26.337 132.825,28.94 131.575,30.19 ; J3.2@97.593,6.191 97.596,6.189 100.637,6.189 J4.2@100.64,6.186 100.632,6.179 100.632,2.657 SGND2.1@100.625,2.65
  Bottom Layer w0.25: C24.1@111.55,41.825 C24.1@111.6,41.875 ; D4.3@111.925,60.8 111.925,56.891 111.975,56.841 ; C16.2@116.113,65.88 C16.2@116.333,66.1 ; C14.2@116.216,30.375 C14.2@116.226,30.365
  Bottom Layer w0.6: C12.2@104.25,13.425 104.275,13.425 104.45,13.25 104.45,13.074 104.625,12.899 U1.3@104.625,11.5 104.625,11.321 106.704,11.321 107.425,10.6 R28.1@107.425,10.575
  Bottom Layer w1: J3.2@97.593,6.191 97.596,6.189 100.637,6.189 J4.2@100.64,6.186 ; D3.1@111.925,30.375 C14.2@116.216,30.375 ; D4.1@111.925,65.88 C16.2@116.113,65.88
  other v1: 104.625,12.525 127.2,24 128,24 128.8,24 127.2,24.8 128,24.8 128.8,24.8 127.2,25.6 128,25.6 128.8,25.6 127.2,26.4 128,26.4 128.8,26.4 127.2,27.2 128,27.2 128.8,27.2 127.2,28 128,28 128.8,28 127.2,28.8 128,28.8 128.8,28.8 127.2,29.6 128,29.6 128.8,29.6 127.2,30.4 128,30.4 128.8,30.4 127.2,31.2 128,31.2 128.8,31.2 127.2,32 128,32 128.8,32 127.2,32.8 128,32.8 128.8,32.8 127.2,33.6 128,33.6 128.8,33.6 127.2,34.4 128,34.4 128.8,34.4 127.2,59.2 128,59.2 128.8,59.2 127.2,60 128,60 128.8,60 127.2,60.8 128,60.8 128.8,60.8 127.2,61.6 128,61.6 128.8,61.6 127.2,62.4 128,62.4 128.8,62.4 127.2,63.2 128,63.2 128.8,63.2 127.2,64 128,64 128.8,64 127.2,64.8 128,64.8 128.8,64.8 127.2,65.6 128,65.6 128.8,65.6 127.2,66.4 128,66.4 128.8,66.4 127.2,67.2 128,67.2 128.8,67.2 127.2,68 128,68 128.8,68 127.2,68.8 128,68.8 128.8,68.8 127.2,69.6 128,69.6 128.8,69.6
TSET: C106.1 R115.1 R116.2 U101.7 | length 5
  Top Layer w0.508: U101.7@37.773,15.857 U101.7@37.819,15.811 ; R115.1@41.084,13.903 R115.1@41.087,13.905
  Top Layer w0.6: C106.1@37.773,14.1 U101.7@37.773,15.857 ; C106.1@37.95,13.9 41.082,13.9 R115.1@41.084,13.903
VB: Q104.2 Q104.4 R12.1 R107.1 R108.1 R120.2 VCC.1 | length 63.8
  Top Layer w0.6: R120.2@40.989,5.175 44.7,5.175 48.475,8.95 68.307,8.95 71.85,12.493 v1(71.85,18.4)
  Bottom Layer w0.9: R107.1@71.85,17.2 R108.1@71.85,19.25 ; R108.1@71.85,19.275 R108.1@71.85,19.25 ; Q104.2@74.65,18.95 72.15,18.95 R108.1@71.85,19.25
  Bottom Layer w1: Q104.2@74.65,18.95 Q104.4@80.45,18.95 ; R12.1@80.3,28.1 80.414,27.986 80.414,18.986 Q104.4@80.45,18.95 ; VCC.1@83.85,20.025 83.65,19.825 81.15,19.825 80.45,19.125 Q104.4@80.45,18.95
VCC: C103.1 C104.1 C115.1 D106.1 Q104.3 Q105.3 R106.1 R108.2 R122.1 R129.2 U101.12 | length 147.2
  Top Layer w0.508: U101.12@35.233,21.257 U101.12@35.267,21.29
  Top Layer w0.6: R122.1@34.475,37.25 34.65,37.075 34.65,36.826 35.559,35.918 35.559,30.175 35.559,23.257 35.384,23.082 C104.1@35.375,23.082 ; U101.12@35.233,21.257 35.233,22.965 C104.1@35.35,23.082
  Bottom Layer w0.45: R129.2@33.15,26.025 33.212,26.087 33.212,28.29 33.222,28.3 Q105.3@33.275,28.3 33.34,28.3 C115.1@34.24,29.2
  Bottom Layer w0.6: R106.1@9.025,48.025 8.875,47.875 D106.1@8.875,46.3 8.275,46.3 7.924,45.949 7.924,38.311 16.827,29.408 16.827,17.998 19.213,15.612 45.505,15.612 ; C115.1@34.925,30.175 34.925,19.15 35.85,18.225 44.575,18.225 45.505,17.295 45.505,15.612 ; 70.392,21.25 70.392,17.253 69.608,16.469 68.119,16.469 67.133,15.484 67.133,13.945 65.787,12.599 48.517,12.599 45.505,15.612
  Bottom Layer w0.9: C103.1@68.975,21.25 70.392,21.25 R108.2@71.85,21.25 Q104.3@74.65,21.25
VD1: D3.2 R22.2 T1.8 | length 20.3
  Top Layer w0.25: T1.8@104.225,40.027 107.15,37.102 107.15,29.675 108.99,27.835 D3.2@111.925,27.835
  Bottom Layer w0.508: R22.2@115.116,27.835 R22.2@115.126,27.825
  Bottom Layer w1: D3.2@111.925,27.835 R22.2@115.116,27.835
VD2: D4.2 R24.2 T1.11 | length 13.2
  Top Layer w0.25: T1.11@104.225,57.73 109.835,63.34 D4.2@111.925,63.34
  Bottom Layer w1: D4.2@111.925,63.34 R24.2@115.075,63.34
VIN: C1.1 C3.1 C25.1 C27.1 C101.2 J1.1 J1.2 Q1.2 Q1.4 Q3.8 Q102.3 R1.2 R123.2 R127.2 Vin.1 | length 144.4
  Top Layer w0.5: Q3.8@42.85,70.55 Q3.8@47.252,70.55 ; Q3.8@49.78,72.55 47.782,72.55 45.789,70.557 47.244,70.557 Q3.8@47.252,70.55 ; C3.1@55.775,66.15 51.905,70.02 47.782,70.02 Q3.8@47.252,70.55
  Top Layer w0.85: Q1.2@7.95,46.1 7.95,51.874 Q1.4@7.95,52
  Top Layer w1: R1.2@2.2,51.425 2.2,54.425 J1.2@4.275,56.5 ; R1.2@2.247,51.472 Q1.4@7.548,51.472 ; Q1.4@7.95,51.874 Q1.4@8.065,51.99 ; C1.1@20.128,57.147 22.314,57.147 23.889,55.573 23.889,24.903 22.095,23.108 22.095,22.833 21.945,22.683 R123.2@21.67,22.683
  Top Layer w2: Vin.1@2.125,66.775 2.125,66.613 4.275,64.463 J1.1@4.275,61.5 ; J1.2@4.275,56.5 J1.1@4.275,61.5 ; Q3.8@42.85,70.55 40.625,72.775 26.375,72.775 19.65,66.05 C1.1@19.65,57.625 15.725,57.625 11.85,61.5 J1.1@4.275,61.5
  Bottom Layer w0.6: Q102.3@14.502,52.925 14.502,56.647 C101.2@14.85,56.995
  other v1: 40.8,68 41.6,68 42.4,68 43.2,68 44,68 44.8,68 45.6,68 46.4,68 40.8,68.8 41.6,68.8 42.4,68.8 43.2,68.8 44,68.8 44.8,68.8 45.6,68.8 46.4,68.8 40.8,69.6 41.6,69.6 42.4,69.6 43.2,69.6 44,69.6 44.8,69.6 45.6,69.6 46.4,69.6 40.8,70.4 41.6,70.4 42.4,70.4 43.2,70.4 44,70.4 44.8,70.4 45.6,70.4 46.4,70.4 40.8,71.2 41.6,71.2 42.4,71.2 43.2,71.2 44,71.2 44.8,71.2 45.6,71.2 46.4,71.2 40.8,72 41.6,72 42.4,72 43.2,72 44,72 44.8,72 45.6,72 46.4,72 40.8,72.8 41.6,72.8 42.4,72.8 43.2,72.8 44,72.8 44.8,72.8 45.6,72.8 46.4,72.8 40.8,73.6 41.6,73.6 42.4,73.6 43.2,73.6 44,73.6 44.8,73.6 45.6,73.6 46.4,73.6
Vout: C18.1 C20.1 C21.1 C22.1 C23.2 C24.2 Inj2.1 J5.2 R29.2 T1.9 T1.10 Vout.1 | length 158.5
  Top Layer w0.25: T1.10@104.225,52.625 T1.9@104.225,45.132 106.126,47.033 131.575,47.033 ; 141.075,39.2 140.95,39.075 140.95,39 ; C22.1@145.4,54.2 145.25,54.05 145.25,51.521 145.155,51.427 145.155,51.1 ; J5.2@145.95,39 140.95,39 ; Vout.1@146.95,46.475 146.95,48.319 145.155,50.113 145.155,51.1 ; 131.575,47.033 131.575,51.375 131.85,51.1 145.155,51.1 ; 131.575,47.033 131.575,42.69 131.575,41.19 133.765,39 140.95,39
  Bottom Layer w0.25: T1.9@104.225,45.132 104.337,45.132 105.444,44.025 C24.2@111.975,44.025 ; T1.10@104.225,52.625 109.459,52.625 111.35,54.516 C23.2@111.35,54.616
  Bottom Layer w0.6: R29.2@116.425,3.725 Inj2.1@119.35,3.725 132.986,3.725 143.075,13.814 C21.1@143.075,18.375 ; C21.1@143.091,18.391 143.091,38.649 143.443,39 J5.2@145.95,39
  other v1: 127.2,41.6 128,41.6 128.8,41.6 127.2,42.4 128,42.4 128.8,42.4 127.2,43.2 128,43.2 128.8,43.2 127.2,44 128,44 128.8,44 127.2,44.8 128,44.8 128.8,44.8 127.2,45.6 128,45.6 128.8,45.6 127.2,46.4 128,46.4 128.8,46.4 127.2,47.2 128,47.2 128.8,47.2 127.2,48 128,48 128.8,48 127.2,48.8 128,48.8 128.8,48.8 127.2,49.6 128,49.6 128.8,49.6 127.2,50.4 128,50.4 128.8,50.4 127.2,51.2 128,51.2 128.8,51.2 127.2,52 128,52 128.8,52
pads on no net: H201.0 H202.0 H203.1 H204.0 H205.0 H206.1 H207.0 H208.0 H209.1 H210.0 H211.0 H212.1 L1.1 L1.6 L1.10 L1.11 Q3. Q4. T1.1 T1.6 T1.7 T1.12

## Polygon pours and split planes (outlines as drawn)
PGND on Int2 (PWR) "INT2_(PWR)_PGND_P084" (solid, remove dead copper, pour order 84): 19.643,28.35 23.425,28.35 25,29.925 25,31.725 26.675,33.4 43.1,33.4 45.975,30.525 45.975,25.625 45.225,24.875 31.2,24.875 30.175,25.9 23.925,25.9 23.275,25.25 20.225,25.25 19.643,25.832
PGND on Int2 (PWR) "INT2_(PWR)_PGND_P081" (solid, remove dead copper, pour order 81): 51.413,41.375 51.413,45.037 50.025,46.425 24.075,46.425 22.775,45.125 22.775,37.225 21.325,35.775 17.821,35.775 16.95,34.904 16.95,33.05 17.8,32.2 23.875,32.2 25.775,34.1 43.188,34.1 45.15,36.062 45.15,37.85 45.975,38.675 47.05,38.675 49.05,40.675 50.713,40.675
PGND on Int2 (PWR) "INT2_(PWR)_PGND_P072" (solid, remove dead copper, pour order 72): 28.75,80.9 28.75,79.025 30,77.775 32.7,77.775 34.05,79.125 59.5,79.125 62.175,76.45 62.175,67.775 63.3,66.65 67.475,66.65 68.45,67.625 68.45,77.475 64.45,81.475 29.325,81.475
VIN on Int2 (PWR) "INT2_(PWR)_VIN_P055" (solid, remove dead copper, pour order 55): 22.275,74.625 18.05,70.4 18.05,59.217 17.483,58.65 17.119,58.65 16.675,59.094 16.675,65.025 12.6,69.1 1.525,69.1 0.475,68.05 0.475,51.575 1.275,50.775 9.15,50.775 9.55,51.175 9.55,56.275 10.25,56.975 12.7,56.975 13.65,56.025 18.975,56.025 20.551,56.001 21.221,56.671 31.675,67.125 50.05,67.125 52.375,64.8 56.8,64.8 57.95,65.95 57.95,69.975 53.3,74.625
PGND on Int2 (PWR) "INT2_(PWR)_PGND_P073" (solid, remove dead copper, pour order 73): 72.05,39.025 73.425,37.65 83.041,37.65 84.838,39.447 84.838,45.937 83.5,47.275 73.557,47.275 72.05,45.768
HS on Int2 (PWR) "INT2_(PWR)_HS_P066" (solid, remove dead copper, pour order 66): 52.125,58.45 47.5,63.075 34.275,63.075 32.925,61.725 32.925,50.35 33.7,49.575 50.193,49.575 52.125,51.507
